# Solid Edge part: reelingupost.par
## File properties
Author: kaisa
Template: iso metric part.par
Last saved by: kaisa
Revision: 9
Application: Solid Edge
Accuracy: 0.990
Username: kaisa
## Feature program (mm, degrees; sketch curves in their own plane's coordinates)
sketch for "unnamed Protrusion 1" plane through (0, 0, 0) normal (0, 0, 1) x-axis (1, 0, 0)
  circle centre (0, 0) radius 1
extrude "unnamed Protrusion 1" add finite 15 along +normal
sketch for "ExtrudedProtrusion_2" plane through (0, 0, 0) normal (1, 0, 0) x-axis (0, 1, 0)
  circle centre (0, 15) radius 2
extrude "ExtrudedProtrusion_2" add finite 3 symmetric
sketch for "ExtrudedCutout_2" plane through (-1.5, 0, 15) normal (-1, 0, 0) x-axis (0, -1, 0)
extrude "ExtrudedCutout_2" cut finite 5 along -normal
fillet "Round_5" radius 0.3
fillet "Round_6" radius 0.39
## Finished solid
Body 1: solid body, 9 faces, 9 edges, 0 vertices.
  Faces by surface: cylinder 3, plane 3, torus 2, blend 1
  Edges by curve: circle 7, intersection 2
Bounding box of the edges (mm; curved faces can reach further): 3.000 x 4.000 x 17.000, from (-1.5, -2, 0) to (1.5, 2, 17).
Cylindrical faces by radius (mm): R1 x1, R1.5 x1, R2 x1
Toroidal faces (ring radius, tube radius in mm): R1.8 r0.3 x2
Planar faces by outward normal: +x 1, -x 1, -z 1
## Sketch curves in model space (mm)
circle centre (0, 0, 15) radius 2
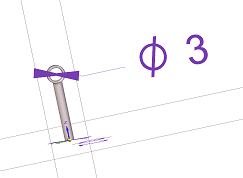
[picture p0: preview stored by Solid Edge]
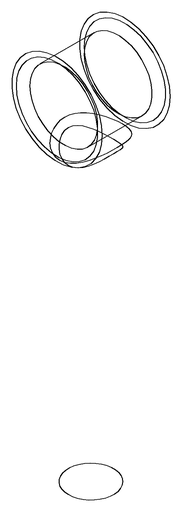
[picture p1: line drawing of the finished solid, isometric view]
